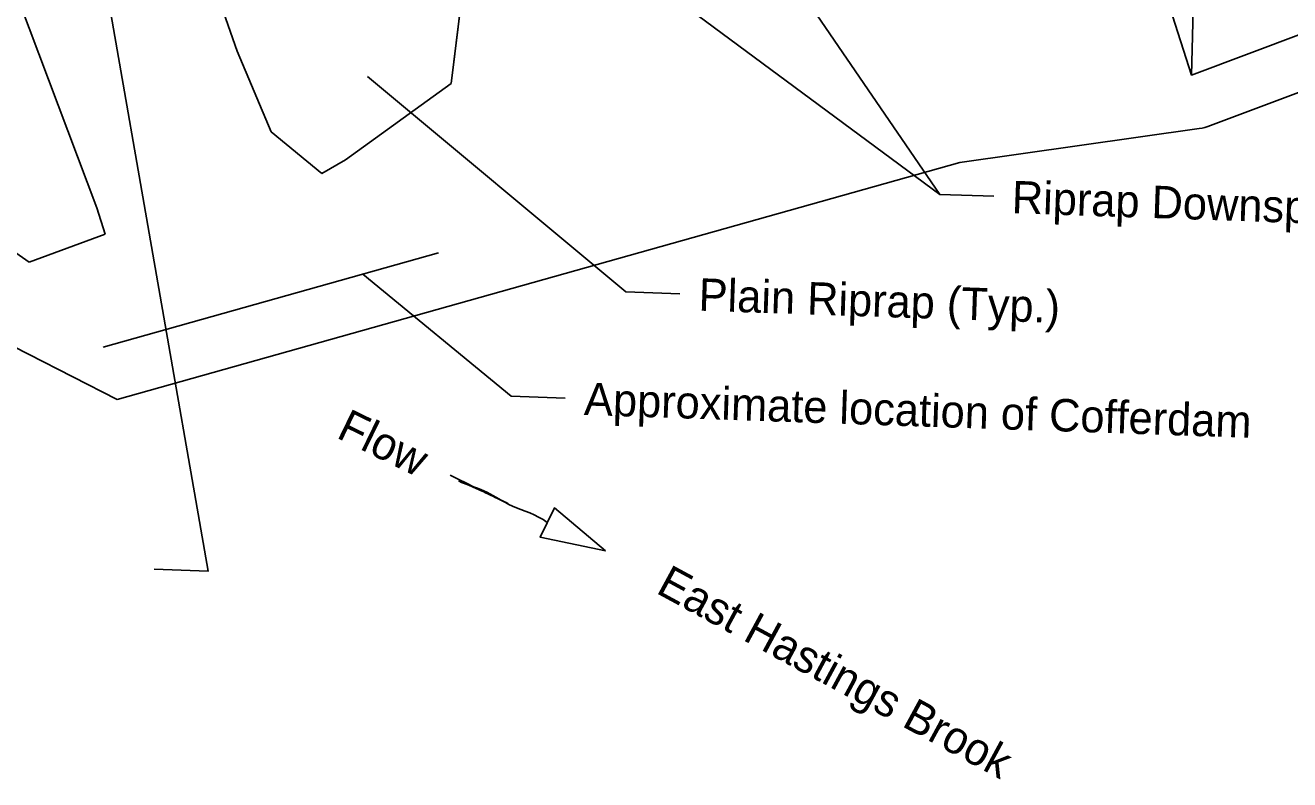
# Model space of a CAD drawing. Extents: x 2191309 to 2193046, y 863659 to 865133.
# Drawn here: x 2192668.4 to 2192785.4, y 863812.7 to 863882.5 of the extents above; entities that cross this region are included whole.
import ezdxf

# ---------------------------------------------------------------- set-up
doc = ezdxf.new("R2010")
doc.units = 0
for name, color, linetype in [('ANNOTATION', 7, 'Continuous'), ('D_Slope_ClearingLimitLine', 7, 'Continuous'), ('D_Slope_Toe', 7, 'Continuous'), ('DIMENSIONS', 7, 'Continuous'), ('H_V CONTROLS', 7, 'Continuous'), ('JUNK', 7, 'Continuous'), ('WATER_DAM', 7, 'Continuous')]:
    doc.layers.add(name, color=color, linetype=linetype)

msp = doc.modelspace()

# ---------------------------------------------------------------- linework, layer by layer
at = {"layer": 'D_Slope_ClearingLimitLine'}
msp.add_line((2192754.85, 863869.78), (2192777, 863872.91), dxfattribs=at)
for points in [[(2192778.06, 863873.18), (2192798.63, 863880.91), (2192815.99, 863887.18), (2192823.44, 863889.37), (2192834.04, 863892.08), (2192837.57, 863893.29)], [(2192652.26, 863860.44), (2192676.91, 863847.87), (2192754.85, 863869.78)]]:
    msp.add_lwpolyline(points, dxfattribs=at)
msp.add_arc((2192776.3, 863877.86), 5, 278.0544, 290.5924, dxfattribs=at)
at = {"layer": 'D_Slope_Toe'}
for p, q in [((2192691.16, 863872.62), (2192695.84, 863868.77)), ((2192660.44, 863866.42), (2192668.76, 863860.55)), ((2192668.76, 863860.55), (2192675.79, 863863.14))]:
    msp.add_line(p, q, dxfattribs=at)
for points in [[(2192872.45, 863907.14), (2192847.31, 863901.92), (2192832.61, 863896.88), (2192822.12, 863894.2), (2192814.44, 863891.94), (2192796.9, 863885.6), (2192776.3, 863877.86), (2192772.03, 863891.16), (2192747.06, 863892.87)], [(2192682.44, 863896.04), (2192688.01, 863880.06), (2192691.16, 863872.62)], [(2192675.79, 863863.14), (2192675.04, 863865.58), (2192666.08, 863889.34)], [(2192695.84, 863868.77), (2192698.04, 863870.03), (2192707.81, 863877.09), (2192709.23, 863888.63)]]:
    msp.add_lwpolyline(points, dxfattribs=at)
at = {"layer": 'DIMENSIONS'}
msp.add_line((2192753.01, 863866.82), (2192697.24, 863948.19), dxfattribs=at)
for points in [[(2192758.01, 863866.65), (2192753.01, 863866.82), (2192695.56, 863909.32)], [(2192680.34, 863832.18), (2192685.34, 863832.01), (2192675.78, 863886.75)], [(2192728.95, 863857.64), (2192723.95, 863857.81), (2192700.08, 863877.72)]]:
    msp.add_lwpolyline(points, dxfattribs=at)
at = {"layer": 'H_V CONTROLS'}
msp.add_line((2192709.23, 863888.63), (2192707.81, 863877.09), dxfattribs=at)
at = {"layer": 'JUNK'}
for p, q in [((2192776.3, 863877.86), (2192777.48, 863926.07)), ((2192675.62, 863852.7), (2192706.64, 863861.42))]:
    msp.add_line(p, q, dxfattribs=at)
msp.add_lwpolyline([(2192718.35, 863848), (2192713.35, 863848.17), (2192699.63, 863859.45)], dxfattribs=at)
at = {"layer": 'WATER_DAM'}
msp.add_lwpolyline([(2192722.09, 863833.86), (2192717.35, 863837.84), (2192716.03, 863835.14)], close=True, dxfattribs=at)
msp.add_open_spline([(2192716.69, 863836.49), (2192715.68, 863837.26), (2192713.21, 863837.91), (2192711.18, 863839.45), (2192708.72, 863840.1), (2192707.7, 863840.87), (2192716.69, 863836.49), (2192707.7, 863840.87)], degree=3, dxfattribs=at)

# ---------------------------------------------------------------- texts
at = {"layer": 'ANNOTATION'}
for s, rotation, p in [('Riprap Downspout (Typ.)', 358.0343, (2192759.63, 863865.09)), ('Plain Riprap (Typ.)', 358.0343, (2192730.66, 863856.08)), ('East Hastings Brook', 331.5684, (2192726.65, 863830.03))]:
    msp.add_text(s, height=3, rotation=rotation, dxfattribs=at).set_placement(p)
at = {"layer": 'JUNK'}
msp.add_text('Approximate location of Cofferdam', height=3, rotation=358.0343, dxfattribs=at).set_placement((2192720.06, 863846.44))
at = {"layer": 'WATER_DAM'}
msp.add_text('Flow', height=3, rotation=334.0254, dxfattribs=at).set_placement((2192697.08, 863844.38))

doc.saveas('drawing.dxf')
